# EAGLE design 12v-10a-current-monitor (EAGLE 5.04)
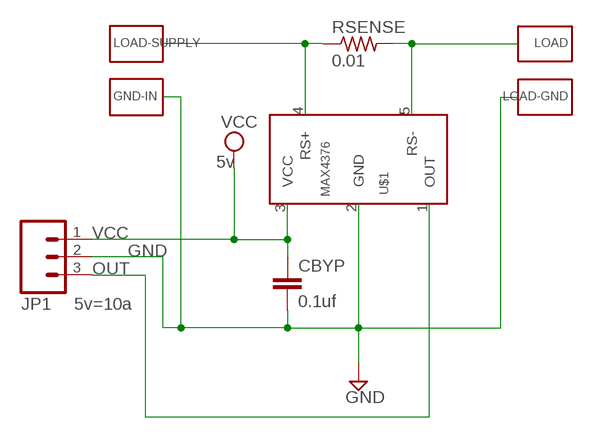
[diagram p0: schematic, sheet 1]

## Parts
CBYP  0.1uf  C-EUC1206  [C1206]
GND-IN  WIREPAD-SMD-NO-VALUE  [WIREPAD-SMD]
JP1  M03POLAR  [MOLEX-1X3]
LOAD  WIREPAD-SMD-NO-VALUE  [WIREPAD-SMD]
LOAD-GND  WIREPAD-SMD-NO-VALUE  [WIREPAD-SMD]
LOAD-SUPPLY  WIREPAD-SMD-NO-VALUE  [WIREPAD-SMD]
RSENSE  0.01  R-US_M1206  [M1206]
U$1  MAX4376  [TSOT23-5]

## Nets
GND: CBYP.2 GND-IN.1(P) JP1.2 LOAD-GND.1(P) U$1.2(GND)
N$1: LOAD.1(P) RSENSE.2 U$1.5(RS-)
N$2: LOAD-SUPPLY.1(P) RSENSE.1 U$1.4(RS+)
OUT: JP1.3 U$1.1(OUT)
VCC: CBYP.1 JP1.1 U$1.3(VCC)

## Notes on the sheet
- 5v
- 5v=10a

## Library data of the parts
CBYP = rcl:C-EU: CAPACITOR, European symbol
GND-IN LOAD LOAD-GND LOAD-SUPPLY = trl:WIREPAD-SMD-NO-VALUE
JP1 = SparkFun:M03: Header 3 Standard 3-pin 0.1" header. Use with straight break away headers (SKU : PRT-00116), right angle break away headers (PRT-00553), swiss pins (PRT-00743), machine pins (PRT-00117), and female headers (PRT-00115). Molex polarized connector foot print use with SKU : PRT-08232 with associated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
RSENSE = rcl:R-US_: RESISTOR, American symbol
U$1 = trl:MAX4376

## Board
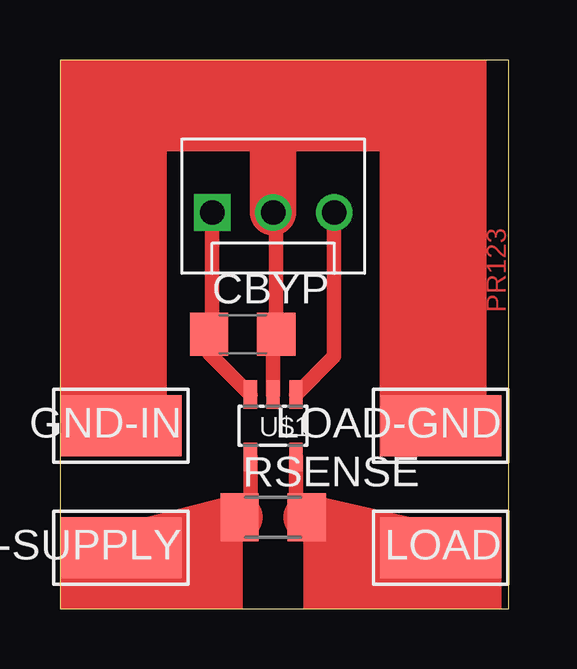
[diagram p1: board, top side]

Size 18.72 x 22.85 mm. Coordinates in mm from the lower left corner, seen from the top.
Outline: 0,0 18.72,0 18.72,22.85 0,22.85 0,0
Copper layers (1*16): Top 0.035mm / dielectric 1.5mm / Bottom 0.035mm
Design rules "default": minimum track width 10mil, minimum drill 24mil, track to track 8mil, track to pad 8mil, pad to pad 8mil, via to via 8mil, smd to smd 8mil, copper to edge 40mil, drill to drill 8mil, minimum pad ring 10mil, minimum via ring 8mil, stop-mask expansion 4mil, vias tented up to drill 0mil, thermal gap 10mil

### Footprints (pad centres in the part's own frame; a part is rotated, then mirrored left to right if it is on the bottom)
C1206 = smd 1.6 x 1.8: 1 -1.4,0; 2 1.4,0
WIREPAD-SMD = smd 2.54 x 5.08: 1 0,0
MOLEX-1X3 = drill 1.016 square: 1 0,0 | drill 1.016 round: 2 2.54,0; 3 5.08,0
M1206 = smd 1.6 x 2: 1 -1.4,0; 2 1.4,0
TSOT23-5 = smd 0.55 x 1.2: 1 -0.95,-1.3; 2 0,-1.3; 3 0.95,-1.3; 4 0.95,1.3; 5 -0.95,1.3

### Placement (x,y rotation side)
CBYP  7.62,11.43 0 top
GND-IN  2.54,7.62 90 top
JP1  6.35,16.51 0 top
LOAD  15.88,2.54 90 top
LOAD-GND  15.88,7.62 90 top
LOAD-SUPPLY  2.54,2.54 90 top
RSENSE  8.89,3.81 0 top
U$1  8.89,7.62 180 top

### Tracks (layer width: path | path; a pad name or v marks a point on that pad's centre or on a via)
GND
  Top 0.61: U$1.2 8.89,11.3 CBYP.2 9.02,16.38 JP1.2
  Top 1.93: 8.89,20.32 JP1.2
  Top 2.54: GND-IN.1 2.54,20.32 8.89,20.32 16.51,20.32 16.51,12.06 16.51,7.62 LOAD-GND.1
N$1
  Top 0.61: U$1.5 9.84,4.26 RSENSE.2
  Top 1.93: RSENSE.2 LOAD.1
N$2
  Top 0.61: U$1.4 7.94,4.26 RSENSE.1
  Top 1.93: RSENSE.1 LOAD-SUPPLY.1
OUT
  Top 0.61: U$1.1 11.43,10.51 JP1.3
VCC
  Top 0.61: CBYP.1 6.35,11.43 | U$1.3 6.22,10.64 CBYP.1 | CBYP.1 6.35,11.56 JP1.1
(copper drawn outside any net)
  shapes: Top area x5

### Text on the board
Top: PR123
